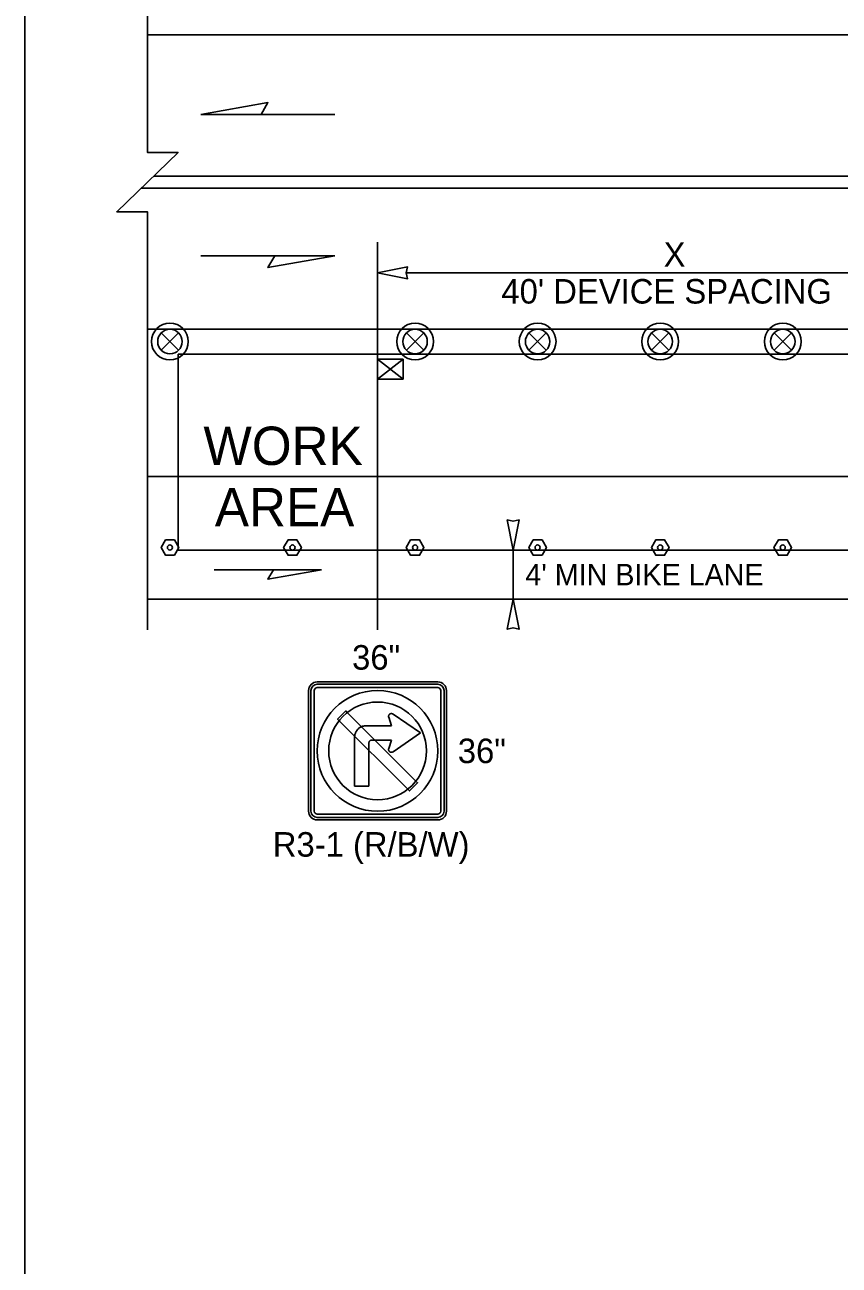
# Model space of a CAD drawing. Extents: x 99958 to 100176, y 99935 to 100011.
# Drawn here: x 100047.875 to 100050.001, y 99972.334 to 99975.571 of the extents above; entities that cross this region are included whole.
import ezdxf

# ---------------------------------------------------------------- set-up
doc = ezdxf.new("R2010")
doc.units = 0
for name, color, linetype in [('RD_ED_ShoulderPavedEdge', 7, 'Continuous'), ('RD_MK_LineDblYellowCenter', 7, 'Continuous'), ('RD_MK_LineEdgeYellow', 7, 'Continuous'), ('RD_MK_LineLane', 7, 'Continuous'), ('TR_SN_ConstructionSigns', 7, 'Continuous'), ('TR_WZ_PortableSignMount5ftMinRed-Wht', 7, 'Continuous'), ('TR_WZ_TrafficSafetyDrum', 7, 'Continuous'), ('TR_WZ_TubularMarker', 7, 'Continuous'), ('TR_WZ_WorkAreaLabel', 7, 'Continuous'), ('TR_WZ_WorkZoneDetails', 7, 'Continuous'), ('TR_WZ_WorkZoneTextCurrent', 7, 'Continuous')]:
    doc.layers.add(name, color=color, linetype=linetype)

msp = doc.modelspace()

# ---------------------------------------------------------------- linework, layer by layer
at = {"layer": 'RD_ED_ShoulderPavedEdge'}
msp.add_line((100048.195, 99974.0724), (100050.5869, 99974.0724), dxfattribs=at)
at = {"layer": 'RD_MK_LineDblYellowCenter'}
for p, q in [((100050.8403, 99975.1764), (100048.2115, 99975.1764)), ((100050.8403, 99975.1444), (100048.1785, 99975.1444))]:
    msp.add_line(p, q, dxfattribs=at)
at = {"layer": 'RD_MK_LineEdgeYellow'}
msp.add_line((100048.195, 99974.3924), (100050.3369, 99974.3924), dxfattribs=at)
at = {"layer": 'RD_MK_LineLane'}
for points in [[(100055.43, 99975.5444), (100048.195, 99975.5444)], [(100055.43, 99974.7764), (100048.195, 99974.7764)]]:
    msp.add_lwpolyline(points, dxfattribs=at)
at = {"layer": 'TR_SN_ConstructionSigns'}
for p, q in [((100048.6159, 99973.5189), (100048.6159, 99973.8339)), ((100048.6159, 99973.8339), (100048.6159, 99973.5189)), ((100048.6159, 99973.8339), (100048.6159, 99973.5189)), ((100048.6222, 99973.8339), (100048.6222, 99973.5189)), ((100048.6309, 99973.5189), (100048.6309, 99973.8339)), ((100048.6384, 99973.8564), (100048.9534, 99973.8564)), ((100048.9534, 99973.8564), (100048.6384, 99973.8564)), ((100048.9534, 99973.8564), (100048.6384, 99973.8564)), ((100048.9534, 99973.8502), (100048.6384, 99973.8502)), ((100048.6384, 99973.8414), (100048.9534, 99973.8414)), ((100048.9609, 99973.8339), (100048.9609, 99973.5189)), ((100048.9697, 99973.5189), (100048.9697, 99973.8339)), ((100048.9759, 99973.8339), (100048.9759, 99973.5189)), ((100048.9759, 99973.5189), (100048.9759, 99973.8339)), ((100048.9759, 99973.5189), (100048.9759, 99973.8339)), ((100048.8247, 99973.7671), (100048.8246, 99973.7663)), ((100048.8246, 99973.7663), (100048.8247, 99973.7655)), ((100048.8248, 99973.7678), (100048.8247, 99973.7671)), ((100048.8247, 99973.7655), (100048.8248, 99973.7647)), ((100048.825, 99973.7686), (100048.8248, 99973.7678)), ((100048.8248, 99973.7647), (100048.825, 99973.764)), ((100048.8253, 99973.7693), (100048.825, 99973.7686)), ((100048.825, 99973.764), (100048.8321, 99973.742)), ((100048.8256, 99973.77), (100048.8253, 99973.7693)), ((100048.826, 99973.7707), (100048.8256, 99973.77)), ((100048.8265, 99973.7713), (100048.826, 99973.7707)), ((100048.827, 99973.7718), (100048.8265, 99973.7713)), ((100048.8276, 99973.7723), (100048.827, 99973.7718)), ((100048.8283, 99973.7728), (100048.8276, 99973.7723)), ((100048.829, 99973.7731), (100048.8283, 99973.7728)), ((100048.8297, 99973.7734), (100048.829, 99973.7731)), ((100048.8304, 99973.7736), (100048.8297, 99973.7734)), ((100048.8312, 99973.7738), (100048.8304, 99973.7736)), ((100048.832, 99973.7738), (100048.8312, 99973.7738)), ((100048.8328, 99973.7738), (100048.832, 99973.7738)), ((100048.8335, 99973.7737), (100048.8328, 99973.7738)), ((100048.8343, 99973.7735), (100048.8335, 99973.7737)), ((100048.835, 99973.7733), (100048.8343, 99973.7735)), ((100048.8357, 99973.7729), (100048.835, 99973.7733)), ((100048.8363, 99973.7725), (100048.8357, 99973.7729)), ((100048.9083, 99973.7233), (100048.8363, 99973.7725)), ((100048.7427, 99973.7309), (100048.7418, 99973.7297)), ((100048.7437, 99973.7321), (100048.7427, 99973.7309)), ((100048.7448, 99973.7332), (100048.7437, 99973.7321)), ((100048.7459, 99973.7343), (100048.7448, 99973.7332)), ((100048.7471, 99973.7353), (100048.7459, 99973.7343)), ((100048.7484, 99973.7363), (100048.7471, 99973.7353)), ((100048.7497, 99973.7371), (100048.7484, 99973.7363)), ((100048.751, 99973.738), (100048.7497, 99973.7371)), ((100048.7524, 99973.7387), (100048.751, 99973.738)), ((100048.7538, 99973.7394), (100048.7524, 99973.7387)), ((100048.7552, 99973.74), (100048.7538, 99973.7394)), ((100048.7567, 99973.7405), (100048.7552, 99973.74)), ((100048.7582, 99973.741), (100048.7567, 99973.7405)), ((100048.7598, 99973.7413), (100048.7582, 99973.741)), ((100048.7613, 99973.7416), (100048.7598, 99973.7413)), ((100048.7629, 99973.7418), (100048.7613, 99973.7416)), ((100048.7644, 99973.742), (100048.7629, 99973.7418)), ((100048.766, 99973.742), (100048.7644, 99973.742)), ((100048.8321, 99973.742), (100048.766, 99973.742)), ((100048.7362, 99973.7151), (100048.736, 99973.7136)), ((100048.736, 99973.7136), (100048.736, 99973.712)), ((100048.736, 99973.712), (100048.736, 99973.5847)), ((100048.7364, 99973.7167), (100048.7362, 99973.7151)), ((100048.7367, 99973.7182), (100048.7364, 99973.7167)), ((100048.737, 99973.7198), (100048.7367, 99973.7182)), ((100048.7375, 99973.7213), (100048.737, 99973.7198)), ((100048.738, 99973.7228), (100048.7375, 99973.7213)), ((100048.7386, 99973.7242), (100048.738, 99973.7228)), ((100048.7393, 99973.7256), (100048.7386, 99973.7242)), ((100048.74, 99973.727), (100048.7393, 99973.7256)), ((100048.7409, 99973.7283), (100048.74, 99973.727)), ((100048.7418, 99973.7297), (100048.7409, 99973.7283)), ((100048.7735, 99973.6978), (100048.7736, 99973.6986)), ((100048.7736, 99973.6986), (100048.7738, 99973.6993)), ((100048.7738, 99973.6993), (100048.7741, 99973.7001)), ((100048.7741, 99973.7001), (100048.7745, 99973.7008)), ((100048.7745, 99973.7008), (100048.7749, 99973.7015)), ((100048.7749, 99973.7015), (100048.7754, 99973.702)), ((100048.7754, 99973.702), (100048.776, 99973.7026)), ((100048.776, 99973.7026), (100048.7766, 99973.7031)), ((100048.7766, 99973.7031), (100048.7772, 99973.7035)), ((100048.7772, 99973.7035), (100048.7779, 99973.7039)), ((100048.7779, 99973.7039), (100048.7787, 99973.7042)), ((100048.7787, 99973.7042), (100048.7794, 99973.7044)), ((100048.7794, 99973.7044), (100048.7802, 99973.7045)), ((100048.7802, 99973.7045), (100048.781, 99973.7046)), ((100048.781, 99973.7046), (100048.8321, 99973.7046)), ((100048.8321, 99973.7046), (100048.825, 99973.6825)), ((100048.8363, 99973.674), (100048.9083, 99973.7233)), ((100048.7735, 99973.697), (100048.7735, 99973.6978)), ((100048.7735, 99973.5847), (100048.7735, 99973.697)), ((100048.8247, 99973.681), (100048.8246, 99973.6802)), ((100048.8246, 99973.6802), (100048.8247, 99973.6795)), ((100048.8248, 99973.6818), (100048.8247, 99973.681)), ((100048.8247, 99973.6795), (100048.8248, 99973.6787)), ((100048.825, 99973.6825), (100048.8248, 99973.6818)), ((100048.8248, 99973.6787), (100048.825, 99973.6779)), ((100048.825, 99973.6779), (100048.8253, 99973.6772)), ((100048.8253, 99973.6772), (100048.8256, 99973.6765)), ((100048.8256, 99973.6765), (100048.826, 99973.6759)), ((100048.826, 99973.6759), (100048.8265, 99973.6752)), ((100048.8265, 99973.6752), (100048.827, 99973.6747)), ((100048.827, 99973.6747), (100048.8276, 99973.6742)), ((100048.8276, 99973.6742), (100048.8283, 99973.6738)), ((100048.8283, 99973.6738), (100048.829, 99973.6734)), ((100048.829, 99973.6734), (100048.8297, 99973.6731)), ((100048.8297, 99973.6731), (100048.8304, 99973.6729)), ((100048.8304, 99973.6729), (100048.8312, 99973.6728)), ((100048.8312, 99973.6728), (100048.832, 99973.6727)), ((100048.832, 99973.6727), (100048.8328, 99973.6727)), ((100048.8328, 99973.6727), (100048.8335, 99973.6728)), ((100048.8335, 99973.6728), (100048.8343, 99973.673)), ((100048.8343, 99973.673), (100048.835, 99973.6733)), ((100048.835, 99973.6733), (100048.8357, 99973.6736)), ((100048.8357, 99973.6736), (100048.8363, 99973.674)), ((100048.736, 99973.5847), (100048.7735, 99973.5847)), ((100048.9534, 99973.5114), (100048.6384, 99973.5114)), ((100048.6384, 99973.5027), (100048.9534, 99973.5027)), ((100048.9534, 99973.4964), (100048.6384, 99973.4964)), ((100048.6384, 99973.4964), (100048.9534, 99973.4964)), ((100048.6384, 99973.4964), (100048.9534, 99973.4964))]:
    msp.add_line(p, q, dxfattribs=at)
msp.add_lwpolyline([(100048.8961, 99973.5975), (100048.717, 99973.7766), (100048.7128, 99973.7808), (100048.6915, 99973.7596), (100048.8748, 99973.5763), (100048.8791, 99973.5721), (100048.9003, 99973.5933), (100048.8961, 99973.5975)], dxfattribs=at)
for radius in [0.1575, 0.1275]:
    msp.add_circle((100048.7959, 99973.6764), radius, dxfattribs=at)
for centre, radius, start, end in [((100048.6384, 99973.8339), 0.0225, 90, 180), ((100048.6384, 99973.8339), 0.0225, 90, 180), ((100048.6384, 99973.8339), 0.0225, 90, 180), ((100048.6384, 99973.8339), 0.0162, 90, 180), ((100048.6384, 99973.8339), 0.0075, 90, 180), ((100048.9534, 99973.8339), 0.0225, 0, 90), ((100048.9534, 99973.8339), 0.0225, 0, 90), ((100048.9534, 99973.8339), 0.0225, 0, 90), ((100048.9534, 99973.8339), 0.0162, 0, 90), ((100048.9534, 99973.8339), 0.0075, 0, 90), ((100048.6384, 99973.5189), 0.0225, 180, 270), ((100048.6384, 99973.5189), 0.0225, 180, 270), ((100048.6384, 99973.5189), 0.0225, 180, 270), ((100048.6384, 99973.5189), 0.0162, 180, 270), ((100048.6384, 99973.5189), 0.0075, 180, 270), ((100048.9534, 99973.5189), 0.0225, 270, 0), ((100048.9534, 99973.5189), 0.0225, 270, 0), ((100048.9534, 99973.5189), 0.0162, 270, 0), ((100048.9534, 99973.5189), 0.0075, 270, 0), ((100048.9534, 99973.5189), 0.0225, 270, 0)]:
    msp.add_arc(centre, radius, start, end, dxfattribs=at)
at = {"layer": 'TR_WZ_PortableSignMount5ftMinRed-Wht'}
for p, q in [((100048.7959, 99974.7124), (100048.7959, 99974.6324)), ((100048.8626, 99974.6464), (100048.7959, 99974.6984)), ((100048.8626, 99974.6984), (100048.7959, 99974.6464)), ((100048.8293, 99974.6725), (100048.8293, 99974.6725)), ((100048.8294, 99974.6724), (100048.8294, 99974.6724))]:
    msp.add_line(p, q, dxfattribs=at)
for points in [[(100048.8626, 99974.6464), (100048.8626, 99974.6984), (100048.7959, 99974.6984), (100048.7959, 99974.6464)], [(100048.7959, 99974.6984), (100048.8626, 99974.6984), (100048.8626, 99974.6464), (100048.7959, 99974.6464)]]:
    msp.add_lwpolyline(points, close=True, dxfattribs=at)
at = {"layer": 'TR_WZ_TrafficSafetyDrum'}
for p, q in [((100048.2313, 99974.7671), (100048.2765, 99974.7218)), ((100048.2765, 99974.7671), (100048.2313, 99974.7218)), ((100048.8713, 99974.7671), (100048.9165, 99974.7218)), ((100048.9165, 99974.7671), (100048.8713, 99974.7218)), ((100049.1913, 99974.7671), (100049.2365, 99974.7218)), ((100049.2365, 99974.7671), (100049.1913, 99974.7218)), ((100049.5113, 99974.7671), (100049.5565, 99974.7218)), ((100049.5565, 99974.7671), (100049.5113, 99974.7218)), ((100049.8313, 99974.7671), (100049.8765, 99974.7218)), ((100049.8765, 99974.7671), (100049.8313, 99974.7218))]:
    msp.add_line(p, q, dxfattribs=at)
for centre, radius in [((100048.2539, 99974.7445), 0.048), ((100048.2539, 99974.7445), 0.048), ((100048.2539, 99974.7445), 0.032), ((100048.8939, 99974.7445), 0.048), ((100048.8939, 99974.7445), 0.048), ((100048.8939, 99974.7445), 0.032), ((100049.2139, 99974.7445), 0.048), ((100049.2139, 99974.7445), 0.048), ((100049.2139, 99974.7445), 0.032), ((100049.5339, 99974.7445), 0.048), ((100049.5339, 99974.7445), 0.048), ((100049.5339, 99974.7445), 0.032), ((100049.8539, 99974.7445), 0.048), ((100049.8539, 99974.7445), 0.048), ((100049.8539, 99974.7445), 0.032)]:
    msp.add_circle(centre, radius, dxfattribs=at)
at = {"layer": 'TR_WZ_TubularMarker'}
for points in [[(100048.2308, 99974.2071), (100048.2424, 99974.2271), (100048.2655, 99974.2271), (100048.277, 99974.2071), (100048.2655, 99974.1871), (100048.2424, 99974.1871)], [(100048.5508, 99974.2071), (100048.5624, 99974.2271), (100048.5855, 99974.2271), (100048.597, 99974.2071), (100048.5855, 99974.1871), (100048.5624, 99974.1871)], [(100048.8708, 99974.2071), (100048.8824, 99974.2271), (100048.9055, 99974.2271), (100048.917, 99974.2071), (100048.9055, 99974.1871), (100048.8824, 99974.1871)], [(100049.1908, 99974.2071), (100049.2024, 99974.2271), (100049.2255, 99974.2271), (100049.237, 99974.2071), (100049.2255, 99974.1871), (100049.2024, 99974.1871)], [(100049.5108, 99974.2071), (100049.5224, 99974.2271), (100049.5455, 99974.2271), (100049.557, 99974.2071), (100049.5455, 99974.1871), (100049.5224, 99974.1871)], [(100049.8308, 99974.2071), (100049.8424, 99974.2271), (100049.8655, 99974.2271), (100049.877, 99974.2071), (100049.8655, 99974.1871), (100049.8424, 99974.1871)]]:
    msp.add_lwpolyline(points, close=True, dxfattribs=at)
for points in [[(100048.2424, 99974.1871), (100048.2655, 99974.1871), (100048.277, 99974.2071), (100048.2655, 99974.2271), (100048.2424, 99974.2271), (100048.2308, 99974.2071), (100048.2424, 99974.1871)], [(100048.5624, 99974.1871), (100048.5855, 99974.1871), (100048.597, 99974.2071), (100048.5855, 99974.2271), (100048.5624, 99974.2271), (100048.5508, 99974.2071), (100048.5624, 99974.1871)], [(100048.8824, 99974.1871), (100048.9055, 99974.1871), (100048.917, 99974.2071), (100048.9055, 99974.2271), (100048.8824, 99974.2271), (100048.8708, 99974.2071), (100048.8824, 99974.1871)], [(100049.2024, 99974.1871), (100049.2255, 99974.1871), (100049.237, 99974.2071), (100049.2255, 99974.2271), (100049.2024, 99974.2271), (100049.1908, 99974.2071), (100049.2024, 99974.1871)], [(100049.5224, 99974.1871), (100049.5455, 99974.1871), (100049.557, 99974.2071), (100049.5455, 99974.2271), (100049.5224, 99974.2271), (100049.5108, 99974.2071), (100049.5224, 99974.1871)], [(100049.8424, 99974.1871), (100049.8655, 99974.1871), (100049.877, 99974.2071), (100049.8655, 99974.2271), (100049.8424, 99974.2271), (100049.8308, 99974.2071), (100049.8424, 99974.1871)]]:
    msp.add_lwpolyline(points, dxfattribs=at)
for centre in [(100048.2539, 99974.2071), (100048.5739, 99974.2071), (100048.8939, 99974.2071), (100049.2139, 99974.2071), (100049.5339, 99974.2071), (100049.8539, 99974.2071)]:
    msp.add_circle(centre, 0.00667, dxfattribs=at)
at = {"layer": 'TR_WZ_WorkZoneDetails'}
for p, q in [((100047.875, 99979.625), (100047.875, 99971.5759)), ((100048.4919, 99975.337), (100048.6848, 99975.337)), ((100048.7959, 99973.9924), (100048.7959, 99975.0036)), ((100048.5276, 99974.9685), (100048.3347, 99974.9685)), ((100050.262, 99974.9236), (100048.8709, 99974.9236)), ((100049.2139, 99974.2004), (100049.0859, 99974.2004)), ((100049.1499, 99974.0724), (100049.1499, 99974.2004)), ((100048.524, 99974.1488), (100048.3697, 99974.1488)), ((100049.2139, 99974.0724), (100049.0859, 99974.0724))]:
    msp.add_line(p, q, dxfattribs=at)
msp.add_lwpolyline([(100048.195, 99973.9924), (100048.195, 99975.083), (100048.115, 99975.083), (100048.275, 99975.2379), (100048.195, 99975.2379), (100048.195, 99976.3285)], dxfattribs=at)
for points in [[(100048.3347, 99975.337), (100048.5097, 99975.3679), (100048.4919, 99975.337)], [(100048.6848, 99974.9685), (100048.5097, 99974.9376), (100048.5276, 99974.9685)], [(100048.7959, 99974.9236), (100048.8745, 99974.9082), (100048.8709, 99974.9236), (100048.8745, 99974.9391)], [(100048.275, 99974.7114), (100048.275, 99974.2004), (100050.4939, 99974.2004), (100050.8139, 99974.2004), (100050.8139, 99974.2004), (100050.8139, 99974.2004), (100051.1339, 99974.2004), (100051.1339, 99974.2004), (100051.1339, 99974.2004), (100051.7739, 99974.2004), (100052.0939, 99974.2004), (100052.5069, 99974.2004), (100052.5069, 99974.2004), (100055.35, 99974.2004), (100055.35, 99974.7114)], [(100049.1499, 99974.2004), (100049.1653, 99974.2791), (100049.1499, 99974.2754), (100049.1345, 99974.2791)], [(100048.6498, 99974.1488), (100048.5097, 99974.1241), (100048.524, 99974.1488)], [(100049.1499, 99974.0724), (100049.1653, 99973.9938), (100049.1499, 99973.9975), (100049.1345, 99973.9938)]]:
    msp.add_lwpolyline(points, close=True, dxfattribs=at)

# ---------------------------------------------------------------- texts
at = {"layer": 'TR_SN_ConstructionSigns'}
for s, p in [('36"', (100048.7295, 99973.8884)), ('36"', (100049.0055, 99973.6445)), ('R3-1 (R/B/W)', (100048.5225, 99973.4004))]:
    msp.add_text(s, height=0.064, rotation=360, dxfattribs=at).set_placement(p)
at = {"layer": 'TR_WZ_WorkAreaLabel'}
for s, p in [('WORK', (100048.3414, 99974.4225)), ('AREA', (100048.3711, 99974.2624))]:
    msp.add_text(s, height=0.1, dxfattribs=at).set_placement(p)
at = {"layer": 'TR_WZ_WorkZoneTextCurrent'}
for s, height, p in [('X', 0.064, (100049.5429, 99974.9397)), ("40' DEVICE SPACING", 0.064, (100049.1193, 99974.8436)), ("4' MIN BIKE LANE", 0.056, (100049.1819, 99974.1084))]:
    msp.add_text(s, height=height, dxfattribs=at).set_placement(p)

doc.saveas('drawing.dxf')
